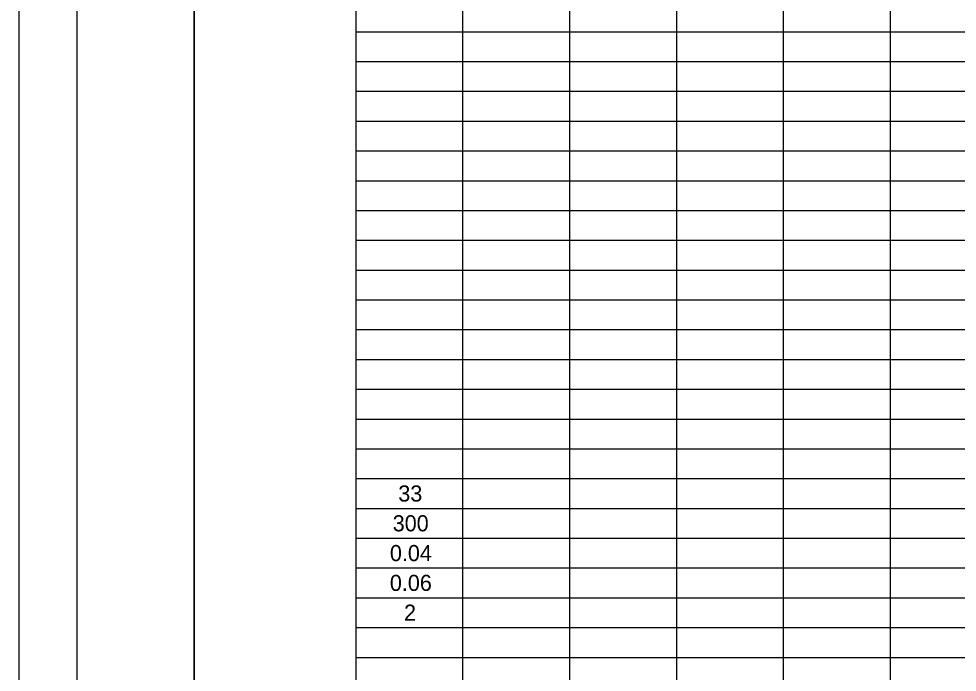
# Model space of a CAD drawing. Extents: x 0 to 34, y 0 to 22.
# Drawn here: x 0 to 8.03, y 10.89 to 16.48 of the extents above; entities that cross this region are included whole.
import ezdxf

# ---------------------------------------------------------------- set-up
doc = ezdxf.new("R2010")
doc.units = 0
for name, color, linetype in [('SH_Border', 7, 'Continuous'), ('SH_Cut_Line', 7, 'Continuous'), ('SH_Text', 7, 'Continuous')]:
    doc.layers.add(name, color=color, linetype=linetype)

msp = doc.modelspace()

# ---------------------------------------------------------------- linework, layer by layer
at = {"layer": 'SH_Border'}
for points in [[(0.5, 21.5), (1.5, 21.5), (1.5, 0.5), (0.5, 0.5)], [(1.5, 21.5), (33.5, 21.5), (33.5, 0.5), (1.5, 0.5)]]:
    msp.add_lwpolyline(points, close=True, dxfattribs=at)
at = {"layer": 'SH_Cut_Line'}
msp.add_lwpolyline([(0, 0), (34, 0), (34, 22), (0, 22)], close=True, dxfattribs=at)
at = {"layer": 'SH_Text'}
for p, q in [((2.8839, 20.9638), (2.8839, 1.8388)), ((3.7989, 20.4538), (3.7989, 1.8388)), ((4.7139, 20.4538), (4.7139, 1.8388)), ((5.6289, 20.4538), (5.6289, 1.8388)), ((6.5439, 20.4538), (6.5439, 1.8388)), ((7.4589, 20.4538), (7.4589, 1.8388)), ((2.8839, 16.3738), (30.6639, 16.3738)), ((2.8839, 16.1188), (30.6639, 16.1188)), ((2.8839, 15.8638), (30.6639, 15.8638)), ((2.8839, 15.6088), (30.6639, 15.6088)), ((2.8839, 15.3538), (30.6639, 15.3538)), ((2.8839, 15.0988), (30.6639, 15.0988)), ((2.8839, 14.8438), (30.6639, 14.8438)), ((2.8839, 14.5888), (30.6639, 14.5888)), ((2.8839, 14.3338), (30.6639, 14.3338)), ((2.8839, 14.0788), (30.6639, 14.0788)), ((2.8839, 13.8238), (30.6639, 13.8238)), ((2.8839, 13.5688), (30.6639, 13.5688)), ((2.8839, 13.3138), (30.6639, 13.3138)), ((2.8839, 13.0588), (30.6639, 13.0588)), ((2.8839, 12.8038), (30.6639, 12.8038)), ((2.8839, 12.5488), (30.6639, 12.5488)), ((2.8839, 12.2938), (30.6639, 12.2938)), ((2.8839, 12.0388), (30.6639, 12.0388)), ((2.8839, 11.7838), (30.6639, 11.7838)), ((2.8839, 11.5288), (30.6639, 11.5288)), ((2.8839, 11.2738), (30.6639, 11.2738)), ((2.8839, 11.0188), (30.6639, 11.0188))]:
    msp.add_line(p, q, dxfattribs=at)

# ---------------------------------------------------------------- texts
for s, p in [('33', (3.2489, 12.3523)), ('300', (3.2009, 12.0973)), ('0.04', (3.1769, 11.8423)), ('0.06', (3.1766, 11.5873)), ('2', (3.2978, 11.3323))]:
    msp.add_text(s, height=0.138, dxfattribs=at).set_placement(p)

doc.saveas('drawing.dxf')
